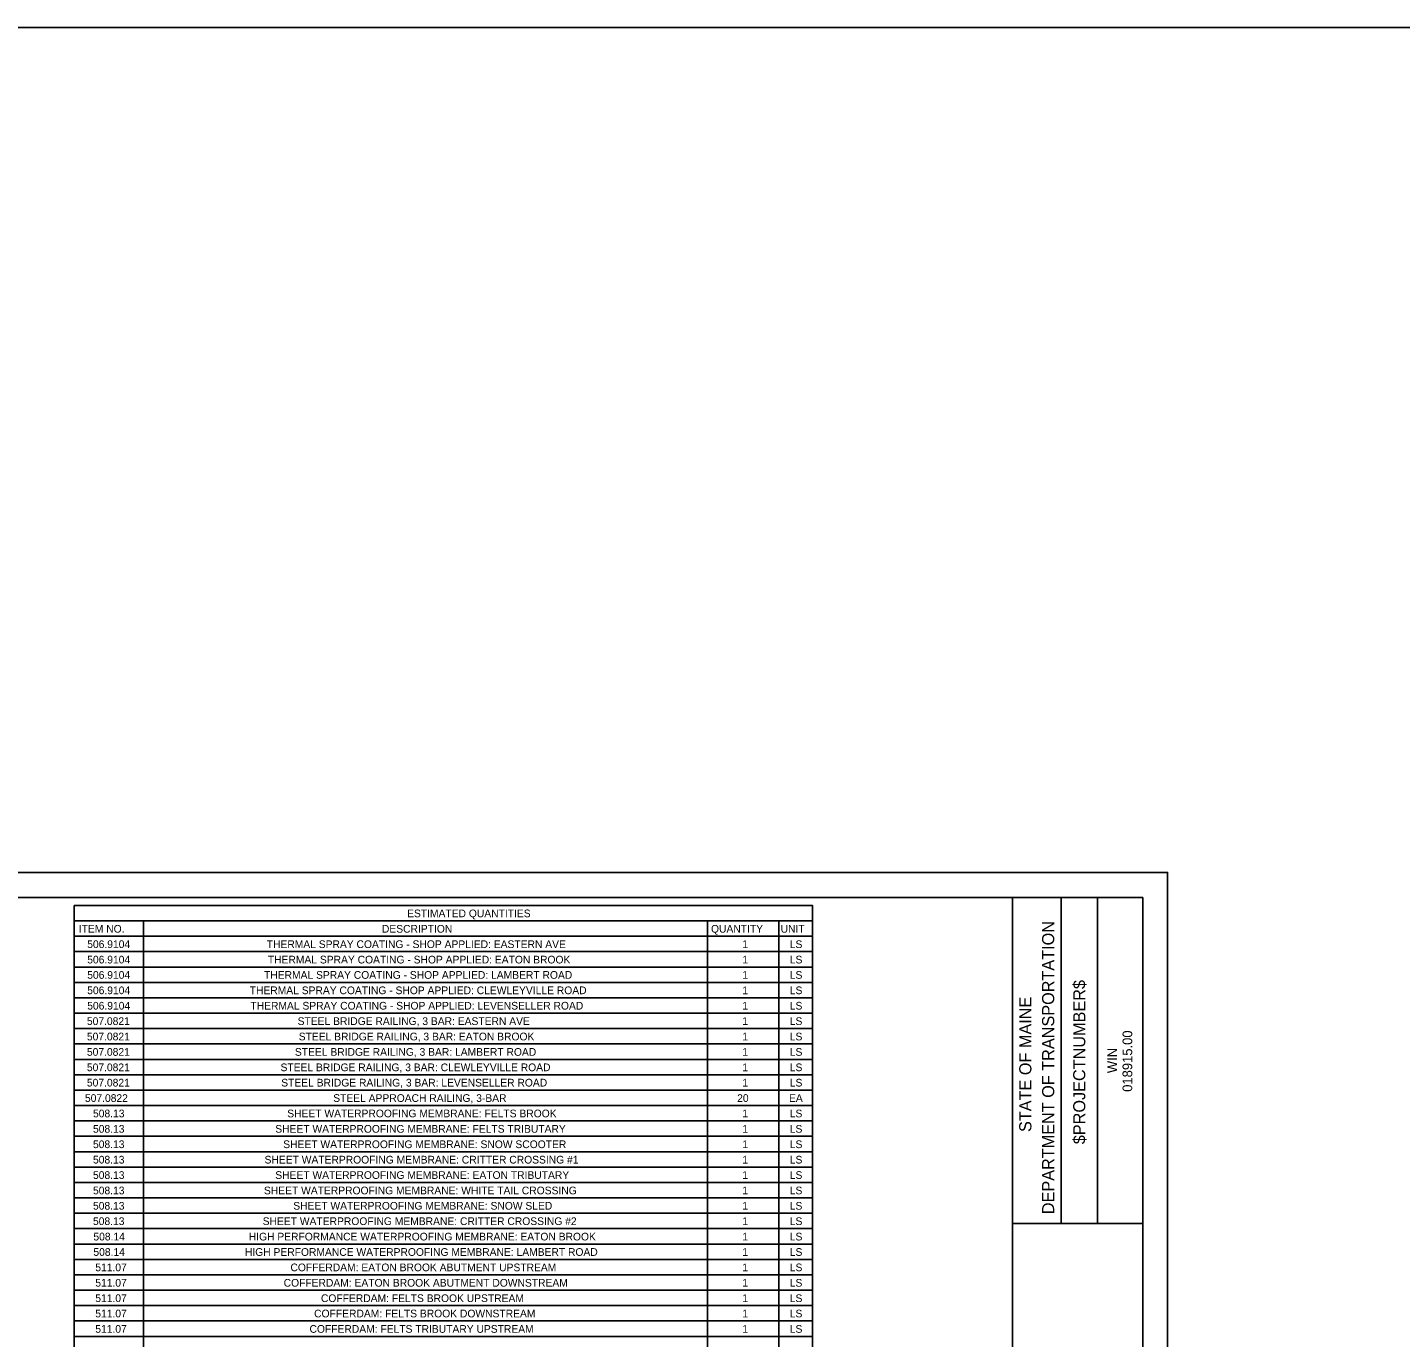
# Model space of a CAD drawing. Extents: x -18.7 to 5.6, y -2.7 to 5.1.
# Drawn here: x -8.539 to -6.783, y 3.422 to 5.098 of the extents above; entities that cross this region are included whole.
import ezdxf

# ---------------------------------------------------------------- set-up
doc = ezdxf.new("R2010")
doc.units = 0
for name, color, linetype in [('ANNOTATION', 7, 'Continuous'), ('BORDER', 7, 'Continuous'), ('Default', 7, 'Continuous'), ('PLOT BOUNDARY', 7, 'Continuous')]:
    doc.layers.add(name, color=color, linetype=linetype)

msp = doc.modelspace()

# ---------------------------------------------------------------- linework, layer by layer
at = {"layer": 'BORDER'}
for p, q in [((-7.2797, 2.2348), (-7.2797, 3.9848)), ((-7.2176, 3.5681), (-7.2176, 3.9847)), ((-7.171, 3.5681), (-7.171, 3.9847)), ((-8.4798, 3.9551), (-7.5355, 3.9551)), ((-8.3912, 3.9551), (-8.3912, 2.2424)), ((-7.6699, 3.9551), (-7.6699, 2.2424)), ((-7.5785, 3.9551), (-7.5785, 2.2424)), ((-8.4798, 3.9354), (-7.5355, 3.9354)), ((-8.4798, 3.9157), (-7.5355, 3.9157)), ((-8.4798, 3.896), (-7.5355, 3.896)), ((-8.4798, 3.8764), (-7.5355, 3.8764)), ((-8.4798, 3.8567), (-7.5355, 3.8567)), ((-8.4798, 3.837), (-7.5355, 3.837)), ((-8.4798, 3.8173), (-7.5355, 3.8173)), ((-8.4798, 3.7976), (-7.5355, 3.7976)), ((-8.4798, 3.7779), (-7.5355, 3.7779)), ((-8.4798, 3.7582), (-7.5355, 3.7582)), ((-8.4798, 3.7386), (-7.5355, 3.7386)), ((-8.4798, 3.7189), (-7.5355, 3.7189)), ((-8.4798, 3.6992), (-7.5355, 3.6992)), ((-8.4798, 3.6795), (-7.5355, 3.6795)), ((-8.4798, 3.6598), (-7.5355, 3.6598)), ((-8.4798, 3.6401), (-7.5355, 3.6401)), ((-8.4798, 3.6204), (-7.5355, 3.6204)), ((-8.4798, 3.6008), (-7.5355, 3.6008)), ((-8.4798, 3.5811), (-7.5355, 3.5811)), ((-7.2797, 3.568), (-7.1131, 3.568)), ((-8.4798, 3.5614), (-7.5355, 3.5614)), ((-8.4798, 3.5417), (-7.5355, 3.5417)), ((-8.4798, 3.522), (-7.5355, 3.522)), ((-8.4798, 3.5023), (-7.5355, 3.5023)), ((-8.4798, 3.4826), (-7.5355, 3.4826)), ((-8.4798, 3.463), (-7.5355, 3.463)), ((-8.4798, 3.4433), (-7.5355, 3.4433)), ((-8.4798, 3.4236), (-7.5355, 3.4236))]:
    msp.add_line(p, q, dxfattribs=at)
for points in [[(-9.7797, 3.9848), (-7.1131, 3.9848), (-7.1131, 2.2348), (-9.7797, 2.2348)], [(-8.4798, 3.9748), (-7.5355, 3.9748), (-7.5355, 2.2424), (-8.4798, 2.2424)]]:
    msp.add_lwpolyline(points, close=True, dxfattribs=at)
at = {"layer": 'Default'}
msp.add_lwpolyline([(-10.8151, 5.0978), (-2.7516, 5.0978), (-2.7516, 1.5028), (-10.8151, 1.5028)], close=True, dxfattribs=at)
at = {"layer": 'PLOT BOUNDARY'}
msp.add_lwpolyline([(-9.9146, 2.1838), (-7.0813, 2.1838), (-7.0813, 4.0171), (-9.9146, 4.0171)], close=True, dxfattribs=at)

# ---------------------------------------------------------------- texts
at = {"layer": 'ANNOTATION'}
for s, height, p in [('506.9104', 0.00984, (-8.463, 3.9203)), ('THERMAL SPRAY COATING - SHOP APPLIED: EASTERN AVE', 0.009843, (-8.2334, 3.9203)), ('1', 0.00984, (-7.6252, 3.9203)), ('LS', 0.00984, (-7.5645, 3.9203)), ('506.9104', 0.00984, (-8.463, 3.9006)), ('THERMAL SPRAY COATING - SHOP APPLIED: EATON BROOK', 0.009843, (-8.232, 3.9006)), ('1', 0.00984, (-7.6252, 3.9006)), ('LS', 0.00984, (-7.5645, 3.9006)), ('506.9104', 0.00984, (-8.463, 3.881)), ('THERMAL SPRAY COATING - SHOP APPLIED: LAMBERT ROAD', 0.009843, (-8.2369, 3.881)), ('1', 0.00984, (-7.6252, 3.881)), ('LS', 0.00984, (-7.5645, 3.881)), ('506.9104', 0.00984, (-8.463, 3.8613)), ('THERMAL SPRAY COATING - SHOP APPLIED: CLEWLEYVILLE ROAD', 0.009843, (-8.2552, 3.8613)), ('1', 0.00984, (-7.6252, 3.8613)), ('LS', 0.00984, (-7.5645, 3.8613)), ('506.9104', 0.00984, (-8.463, 3.8416)), ('THERMAL SPRAY COATING - SHOP APPLIED: LEVENSELLER ROAD', 0.009843, (-8.2543, 3.8416)), ('1', 0.00984, (-7.6252, 3.8416)), ('LS', 0.00984, (-7.5645, 3.8416)), ('507.0821', 0.00984, (-8.4634, 3.8219)), ('STEEL BRIDGE RAILING, 3 BAR: EASTERN AVE', 0.009843, (-8.1939, 3.8219)), ('1', 0.00984, (-7.6252, 3.8219)), ('LS', 0.00984, (-7.5645, 3.8219)), ('507.0821', 0.00984, (-8.4634, 3.8022)), ('STEEL BRIDGE RAILING, 3 BAR: EATON BROOK', 0.009843, (-8.1925, 3.8022)), ('1', 0.00984, (-7.6252, 3.8022)), ('LS', 0.00984, (-7.5645, 3.8022)), ('507.0821', 0.00984, (-8.4634, 3.7825)), ('STEEL BRIDGE RAILING, 3 BAR: LAMBERT ROAD', 0.009843, (-8.1974, 3.7825)), ('1', 0.00984, (-7.6252, 3.7825)), ('LS', 0.00984, (-7.5645, 3.7825)), ('507.0821', 0.00984, (-8.4634, 3.7628)), ('STEEL BRIDGE RAILING, 3 BAR: CLEWLEYVILLE ROAD', 0.009843, (-8.2158, 3.7628)), ('1', 0.00984, (-7.6252, 3.7628)), ('LS', 0.00984, (-7.5645, 3.7628)), ('507.0821', 0.00984, (-8.4634, 3.7432)), ('STEEL BRIDGE RAILING, 3 BAR: LEVENSELLER ROAD', 0.009843, (-8.2149, 3.7432)), ('1', 0.00984, (-7.6252, 3.7432)), ('LS', 0.00984, (-7.5645, 3.7432)), ('507.0822', 0.00984, (-8.4659, 3.7235)), ('STEEL APPROACH RAILING, 3-BAR', 0.009843, (-8.1484, 3.7235)), ('20', 0.00984, (-7.6318, 3.7235)), ('EA', 0.00984, (-7.5655, 3.7235)), ('508.13', 0.00984, (-8.4556, 3.7038)), ('SHEET WATERPROOFING MEMBRANE: FELTS BROOK', 0.009843, (-8.2072, 3.7038)), ('1', 0.00984, (-7.6252, 3.7038)), ('LS', 0.00984, (-7.5645, 3.7038)), ('508.13', 0.00984, (-8.4556, 3.6841)), ('SHEET WATERPROOFING MEMBRANE: FELTS TRIBUTARY', 0.009843, (-8.2225, 3.6841)), ('1', 0.00984, (-7.6252, 3.6841)), ('LS', 0.00984, (-7.5645, 3.6841)), ('508.13', 0.00984, (-8.4556, 3.6644)), ('SHEET WATERPROOFING MEMBRANE: SNOW SCOOTER', 0.009843, (-8.2123, 3.6644)), ('1', 0.00984, (-7.6252, 3.6644)), ('LS', 0.00984, (-7.5645, 3.6644)), ('508.13', 0.00984, (-8.4556, 3.6447)), ('SHEET WATERPROOFING MEMBRANE: CRITTER CROSSING #1', 0.009843, (-8.2362, 3.6447)), ('1', 0.00984, (-7.6252, 3.6447)), ('LS', 0.00984, (-7.5645, 3.6447)), ('508.13', 0.00984, (-8.4556, 3.625)), ('SHEET WATERPROOFING MEMBRANE: EATON TRIBUTARY', 0.009843, (-8.2225, 3.625)), ('1', 0.00984, (-7.6252, 3.625)), ('LS', 0.00984, (-7.5645, 3.625)), ('508.13', 0.00984, (-8.4556, 3.6053)), ('SHEET WATERPROOFING MEMBRANE: WHITE TAIL CROSSING', 0.009843, (-8.237, 3.6053)), ('1', 0.00984, (-7.6252, 3.6053)), ('LS', 0.00984, (-7.5645, 3.6053)), ('508.13', 0.00984, (-8.4556, 3.5857)), ('SHEET WATERPROOFING MEMBRANE: SNOW SLED', 0.009843, (-8.1995, 3.5857)), ('1', 0.00984, (-7.6252, 3.5857)), ('LS', 0.00984, (-7.5645, 3.5857)), ('508.13', 0.00984, (-8.4556, 3.566)), ('SHEET WATERPROOFING MEMBRANE: CRITTER CROSSING #2', 0.009843, (-8.2386, 3.566)), ('1', 0.00984, (-7.6252, 3.566)), ('LS', 0.00984, (-7.5645, 3.566)), ('508.14', 0.00984, (-8.4551, 3.5463)), ('HIGH PERFORMANCE WATERPROOFING MEMBRANE: EATON BROOK', 0.009843, (-8.2564, 3.5463)), ('1', 0.00984, (-7.6252, 3.5463)), ('LS', 0.00984, (-7.5645, 3.5463)), ('508.14', 0.00984, (-8.4551, 3.5266)), ('HIGH PERFORMANCE WATERPROOFING MEMBRANE: LAMBERT ROAD', 0.009843, (-8.2613, 3.5266)), ('1', 0.00984, (-7.6252, 3.5266)), ('LS', 0.00984, (-7.5645, 3.5266)), ('511.07', 0.00984, (-8.4527, 3.5069)), ('COFFERDAM: EATON BROOK ABUTMENT UPSTREAM', 0.009843, (-8.2031, 3.5069)), ('1', 0.00984, (-7.6252, 3.5069)), ('LS', 0.00984, (-7.5645, 3.5069)), ('511.07', 0.00984, (-8.4527, 3.4872)), ('COFFERDAM: EATON BROOK ABUTMENT DOWNSTREAM', 0.009843, (-8.2118, 3.4872)), ('1', 0.00984, (-7.6252, 3.4872)), ('LS', 0.00984, (-7.5645, 3.4872)), ('511.07', 0.00984, (-8.4527, 3.4675)), ('COFFERDAM: FELTS BROOK UPSTREAM', 0.009843, (-8.1641, 3.4675)), ('1', 0.00984, (-7.6252, 3.4675)), ('LS', 0.00984, (-7.5645, 3.4675)), ('511.07', 0.00984, (-8.4527, 3.4479)), ('COFFERDAM: FELTS BROOK DOWNSTREAM', 0.009843, (-8.1728, 3.4479)), ('1', 0.00984, (-7.6252, 3.4479)), ('LS', 0.00984, (-7.5645, 3.4479)), ('511.07', 0.00984, (-8.4527, 3.4282)), ('COFFERDAM: FELTS TRIBUTARY UPSTREAM', 0.009843, (-8.1787, 3.4282)), ('1', 0.00984, (-7.6252, 3.4282)), ('LS', 0.00984, (-7.5645, 3.4282))]:
    msp.add_text(s, height=height, dxfattribs=at).set_placement(p)
at = {"layer": 'BORDER'}
for s, height, p in [('ESTIMATED QUANTITIES', 0.009843, (-8.0539, 3.9597)), ('ITEM NO.', 0.00984, (-8.4738, 3.94)), ('DESCRIPTION', 0.009843, (-8.0861, 3.94)), ('QUANTITY', 0.00984, (-7.6652, 3.94)), ('UNIT', 0.00984, (-7.5762, 3.94))]:
    msp.add_text(s, height=height, dxfattribs=at).set_placement(p)
for s, height, p in [('DEPARTMENT OF TRANSPORTATION', 0.015529, (-7.2263, 3.5799)), ('$PROJECTNUMBER$', 0.015529, (-7.1865, 3.6694)), ('STATE OF MAINE', 0.015529, (-7.2555, 3.685)), ('018915.00', 0.01242, (-7.1265, 3.7364)), ('WIN', 0.01242, (-7.1458, 3.7603))]:
    msp.add_text(s, height=height, rotation=90, dxfattribs=at).set_placement(p)

doc.saveas('drawing.dxf')
